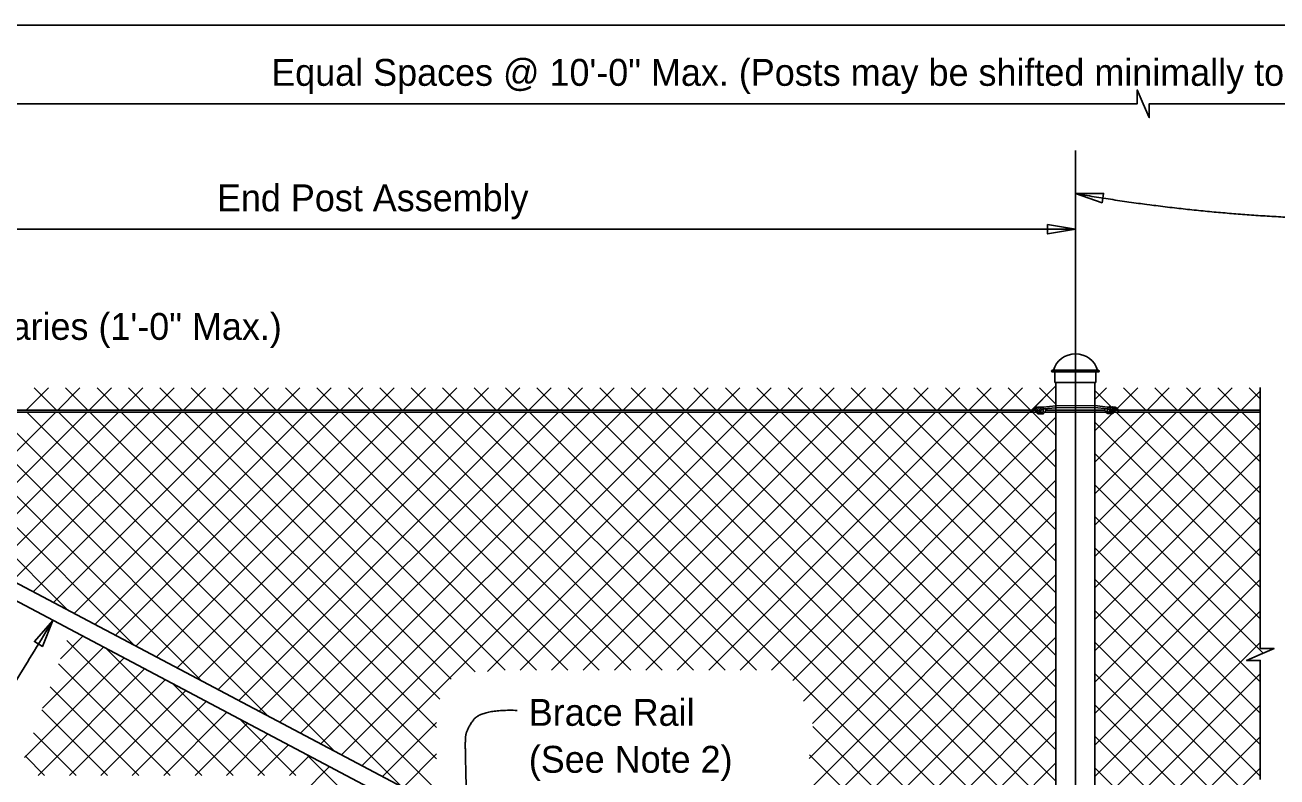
# Model space of a CAD drawing. Extents: x 0 to 72.1, y -15.2 to 30.1.
# Drawn here: x 6.75 to 16.14, y 22.36 to 28 of the extents above; entities that cross this region are included whole.
import ezdxf

# ---------------------------------------------------------------- set-up
doc = ezdxf.new("R2010")
doc.units = 0
for name, color, linetype in [('ActivePts-ConstElements', 7, 'Continuous'), ('Border', 7, 'Continuous'), ('Patterning', 7, 'Continuous'), ('PlotBorder_dp', 7, 'Continuous'), ('SheetBorder_dp', 7, 'Continuous'), ('SheetLines_dp', 7, 'Continuous'), ('TextMisc', 7, 'Continuous')]:
    doc.layers.add(name, color=color, linetype=linetype)

msp = doc.modelspace()

# ---------------------------------------------------------------- linework, layer by layer
at = {"layer": 'ActivePts-ConstElements'}
msp.add_lwpolyline([(0.016, 2.0538), (41.0666, 2.0538), (41.0666, 27.9999), (0.016, 27.9999)], close=True, dxfattribs=at)
at = {"layer": 'Border'}
for p, q in [((14.4852, 25.1116), (14.7769, 25.1116)), ((14.4852, 25.0969), (14.7769, 25.0969))]:
    msp.add_line(p, q, dxfattribs=at)
at = {"layer": 'Patterning'}
for p, q in [((6.761, 25.1116), (6.9276, 25.2783)), ((6.8202, 25.2783), (6.9869, 25.1116)), ((6.9967, 25.1116), (7.1633, 25.2783)), ((7.0559, 25.2783), (7.2226, 25.1116)), ((7.2324, 25.1116), (7.3991, 25.2783)), ((7.2916, 25.2783), (7.4583, 25.1116)), ((7.4681, 25.1116), (7.6348, 25.2783)), ((7.5273, 25.2783), (7.694, 25.1116)), ((7.7038, 25.1116), (7.8705, 25.2783)), ((7.763, 25.2783), (7.9297, 25.1116)), ((7.9395, 25.1116), (8.1062, 25.2783)), ((7.9987, 25.2783), (8.1654, 25.1116)), ((8.1752, 25.1116), (8.3419, 25.2783)), ((8.2344, 25.2783), (8.4011, 25.1116)), ((8.4109, 25.1116), (8.5776, 25.2783)), ((8.4701, 25.2783), (8.6368, 25.1116)), ((8.6466, 25.1116), (8.8133, 25.2783)), ((8.7058, 25.2783), (8.8725, 25.1116)), ((8.8823, 25.1116), (9.049, 25.2783)), ((8.9415, 25.2783), (9.1082, 25.1116)), ((9.118, 25.1116), (9.2847, 25.2783)), ((9.1772, 25.2783), (9.3439, 25.1116)), ((9.3537, 25.1116), (9.5204, 25.2783)), ((9.4129, 25.2783), (9.5796, 25.1116)), ((9.5894, 25.1116), (9.7561, 25.2783)), ((9.6486, 25.2783), (9.8153, 25.1116)), ((9.8251, 25.1116), (9.9918, 25.2783)), ((9.8843, 25.2783), (10.051, 25.1116)), ((10.0608, 25.1116), (10.2275, 25.2783)), ((10.12, 25.2783), (10.2867, 25.1116)), ((10.2965, 25.1116), (10.4632, 25.2783)), ((10.3557, 25.2783), (10.5224, 25.1116)), ((10.5322, 25.1116), (10.6989, 25.2783)), ((10.5914, 25.2783), (10.7581, 25.1116)), ((10.7679, 25.1116), (10.9346, 25.2783)), ((10.8271, 25.2783), (10.9938, 25.1116)), ((11.0036, 25.1116), (11.1703, 25.2783)), ((11.0628, 25.2783), (11.2295, 25.1116)), ((11.2393, 25.1116), (11.406, 25.2783)), ((11.2985, 25.2783), (11.4652, 25.1116)), ((11.475, 25.1116), (11.6417, 25.2783)), ((11.5342, 25.2783), (11.7009, 25.1116)), ((11.7107, 25.1116), (11.8774, 25.2783)), ((11.7699, 25.2783), (11.9366, 25.1116)), ((11.9464, 25.1116), (12.1131, 25.2783)), ((12.0057, 25.2783), (12.1723, 25.1116)), ((12.1821, 25.1116), (12.3488, 25.2783)), ((12.2414, 25.2783), (12.408, 25.1116)), ((12.352, 23.1602), (14.4852, 25.2934)), ((12.4178, 25.1116), (12.5845, 25.2783)), ((12.4771, 25.2783), (12.6437, 25.1116)), ((12.6535, 25.1116), (12.8202, 25.2783)), ((12.7128, 25.2783), (12.8794, 25.1116)), ((12.8892, 25.1116), (13.0559, 25.2783)), ((12.9485, 25.2783), (13.1151, 25.1116)), ((13.1249, 25.1116), (13.2916, 25.2783)), ((13.1842, 25.2783), (13.3508, 25.1116)), ((13.3606, 25.1116), (13.5273, 25.2783)), ((13.4199, 25.2783), (13.5865, 25.1116)), ((13.5963, 25.1116), (13.763, 25.2783)), ((13.6556, 25.2783), (13.8222, 25.1116)), ((13.832, 25.1116), (13.9987, 25.2783)), ((13.8913, 25.2783), (14.0579, 25.1116)), ((14.0677, 25.1116), (14.2344, 25.2783)), ((14.127, 25.2783), (14.2936, 25.1116)), ((14.3035, 25.1116), (14.4701, 25.2783)), ((14.3627, 25.2783), (14.4852, 25.1557)), ((14.7769, 25.1917), (14.8635, 25.2783)), ((14.9441, 25.1232), (15.0992, 25.2783)), ((14.9918, 25.2783), (15.1584, 25.1116)), ((15.1682, 25.1116), (15.3349, 25.2783)), ((15.2275, 25.2783), (15.3941, 25.1116)), ((15.4039, 25.1116), (15.5706, 25.2783)), ((15.4632, 25.2783), (15.6298, 25.1116)), ((15.6396, 25.1116), (15.8063, 25.2783)), ((15.6989, 25.2783), (15.8655, 25.1116)), ((15.9346, 25.2783), (16.018, 25.1949)), ((14.7769, 25.2575), (14.8992, 25.1352)), ((15.8753, 25.1116), (16.018, 25.2543)), ((5.8231, 25.0969), (7.5737, 23.3463)), ((6.0412, 24.1562), (6.9819, 25.0969)), ((6.0588, 25.0969), (8.0736, 23.0821)), ((6.1954, 24.0747), (7.2176, 25.0969)), ((6.2945, 25.0969), (8.5734, 22.818)), ((6.3496, 23.9932), (7.4533, 25.0969)), ((6.5038, 23.9117), (7.689, 25.0969)), ((6.5302, 25.0969), (9.0733, 22.5538)), ((6.658, 23.8302), (7.9247, 25.0969)), ((6.7659, 25.0969), (9.5731, 22.2897)), ((6.8122, 23.7487), (8.1604, 25.0969)), ((6.9665, 23.6672), (8.3961, 25.0969)), ((7.0016, 25.0969), (9.8384, 22.2601)), ((7.1207, 23.5857), (8.6318, 25.0969)), ((7.2373, 25.0969), (9.8384, 22.4958)), ((7.2749, 23.5042), (8.8675, 25.0969)), ((7.4291, 23.4227), (9.1033, 25.0969)), ((7.473, 25.0969), (9.8384, 22.7315)), ((7.5833, 23.3412), (9.339, 25.0969)), ((7.7087, 25.0969), (9.8627, 22.9429)), ((7.7375, 23.2597), (9.5747, 25.0969)), ((7.8917, 23.1782), (9.8104, 25.0969)), ((7.9444, 25.0969), (9.9473, 23.0941)), ((8.0459, 23.0968), (10.0461, 25.0969)), ((8.1801, 25.0969), (10.1284, 23.1486)), ((8.2001, 23.0153), (10.2818, 25.0969)), ((8.3543, 22.9338), (10.5175, 25.0969)), ((8.4158, 25.0969), (10.3525, 23.1602)), ((8.5085, 22.8523), (10.7532, 25.0969)), ((8.6515, 25.0969), (10.5883, 23.1602)), ((8.6628, 22.7708), (10.9889, 25.0969)), ((8.817, 22.6893), (11.2246, 25.0969)), ((8.8872, 25.0969), (10.824, 23.1602)), ((8.9712, 22.6078), (11.4603, 25.0969)), ((9.1229, 25.0969), (11.0597, 23.1602)), ((9.1254, 22.5263), (11.696, 25.0969)), ((9.2796, 22.4448), (11.9317, 25.0969)), ((9.3586, 25.0969), (11.2954, 23.1602)), ((9.5943, 25.0969), (11.5311, 23.1602)), ((9.83, 25.0969), (11.7668, 23.1602)), ((10.0657, 25.0969), (12.0025, 23.1602)), ((10.2203, 23.1498), (12.1674, 25.0969)), ((10.3015, 25.0969), (12.2382, 23.1602)), ((10.4664, 23.1602), (12.4031, 25.0969)), ((10.5372, 25.0969), (14.4852, 21.1488)), ((10.7021, 23.1602), (12.6388, 25.0969)), ((10.7729, 25.0969), (14.4852, 21.3845)), ((10.9378, 23.1602), (12.8745, 25.0969)), ((11.0086, 25.0969), (14.4852, 21.6202)), ((11.1735, 23.1602), (13.1102, 25.0969)), ((11.2443, 25.0969), (14.4852, 21.8559)), ((11.4092, 23.1602), (13.3459, 25.0969)), ((11.48, 25.0969), (14.4852, 22.0916)), ((11.6449, 23.1602), (13.5816, 25.0969)), ((11.7157, 25.0969), (14.4852, 22.3273)), ((11.8806, 23.1602), (13.8173, 25.0969)), ((11.9514, 25.0969), (14.4852, 22.563)), ((12.1163, 23.1602), (14.053, 25.0969)), ((12.1163, 23.1602), (14.053, 25.0969)), ((12.1871, 25.0969), (14.4852, 22.7987)), ((12.4228, 25.0969), (14.4852, 23.0344)), ((12.6585, 25.0969), (14.4852, 23.2701)), ((12.8942, 25.0969), (14.4852, 23.5058)), ((13.1299, 25.0969), (14.4852, 23.7415)), ((13.3656, 25.0969), (14.4852, 23.9772)), ((13.6013, 25.0969), (14.4852, 24.2129)), ((13.837, 25.0969), (14.4852, 24.4486)), ((14.0727, 25.0969), (14.4852, 24.6843)), ((14.3084, 25.0969), (14.4852, 24.92)), ((14.7769, 24.0132), (15.8606, 25.0969)), ((14.7769, 24.4846), (15.3892, 25.0969)), ((14.7769, 24.7203), (15.1535, 25.0969)), ((14.7769, 24.956), (14.9064, 25.0855)), ((14.7813, 24.2534), (15.6249, 25.0969)), ((14.9325, 25.1116), (14.937, 25.1161)), ((14.9375, 25.0969), (16.018, 24.0164)), ((15.1732, 25.0969), (16.018, 24.2521)), ((15.4089, 25.0969), (16.018, 24.4878)), ((15.6446, 25.0969), (16.018, 24.7235)), ((15.8803, 25.0969), (16.018, 24.9592)), ((12.5111, 23.0836), (14.4852, 25.0577)), ((14.7769, 25.0218), (16.018, 23.7807)), ((14.7769, 23.7775), (16.018, 25.0186)), ((5.7678, 24.9165), (7.0739, 23.6104)), ((12.5916, 22.9284), (14.4852, 24.822)), ((14.7769, 24.7861), (16.018, 23.545)), ((14.7769, 23.5418), (16.018, 24.7829)), ((12.6599, 22.761), (14.4852, 24.5863)), ((14.7769, 24.5503), (16.0391, 23.2882)), ((14.7769, 23.3061), (16.018, 24.5472)), ((12.6327, 22.4981), (14.4852, 24.3506)), ((14.7769, 24.3146), (16.018, 23.0736)), ((14.7769, 23.0704), (16.018, 24.3115)), ((11.5927, 21.2224), (14.4852, 24.1149)), ((14.7769, 24.0789), (16.018, 22.8379)), ((14.7769, 22.8347), (16.018, 24.0758)), ((11.7469, 21.1409), (14.4852, 23.8792)), ((14.7769, 23.8432), (16.018, 22.6022)), ((14.7769, 22.599), (16.018, 23.8401)), ((11.9012, 21.0594), (14.4852, 23.6435)), ((14.7769, 23.6075), (16.018, 22.3665)), ((14.7769, 22.3633), (16.018, 23.6044)), ((7.0166, 23.246), (7.1861, 23.4155)), ((12.0554, 20.9779), (14.4852, 23.4078)), ((6.8822, 22.8758), (7.3403, 23.334)), ((7.0662, 23.3824), (8.0769, 22.3717)), ((7.3615, 23.3228), (8.3126, 22.3717)), ((14.7769, 23.3718), (16.018, 22.1307)), ((14.7769, 22.1276), (16.018, 23.3687)), ((6.7477, 22.5056), (7.4945, 23.2525)), ((7.0034, 23.2095), (7.8412, 22.3717)), ((6.8494, 22.3717), (7.6488, 23.171)), ((12.2096, 20.8964), (14.4852, 23.1721)), ((14.7769, 23.1361), (16.018, 21.895)), ((14.7769, 21.8919), (16.018, 23.133)), ((6.9406, 23.0366), (7.6055, 22.3717)), ((7.0851, 22.3717), (7.803, 23.0895)), ((7.8614, 23.0586), (8.5483, 22.3717)), ((7.3208, 22.3717), (7.9572, 23.008)), ((7.5565, 22.3717), (8.1114, 22.9265)), ((12.3638, 20.815), (14.4852, 22.9364)), ((6.8778, 22.8637), (7.3698, 22.3717)), ((7.7922, 22.3717), (8.2656, 22.845)), ((14.7769, 22.9004), (16.018, 21.6593)), ((14.7769, 21.6562), (16.018, 22.8973)), ((8.0279, 22.3717), (8.4198, 22.7635)), ((8.3612, 22.7945), (8.784, 22.3717)), ((9.4338, 22.3633), (9.8384, 22.768)), ((12.6609, 22.7374), (14.4852, 20.9131)), ((6.815, 22.6908), (7.1341, 22.3717)), ((8.2636, 22.3717), (8.574, 22.682)), ((12.518, 20.7335), (14.4852, 22.7007)), ((14.7769, 22.6647), (16.018, 21.4236)), ((14.7769, 21.4205), (16.018, 22.6616)), ((8.4993, 22.3717), (8.7282, 22.6006)), ((6.7521, 22.5179), (6.8984, 22.3717)), ((8.735, 22.3717), (8.8824, 22.5191)), ((8.861, 22.5304), (11.9317, 19.4597)), ((9.588, 22.2818), (9.8384, 22.5323)), ((12.6374, 22.5252), (14.4852, 20.6774)), ((12.6722, 20.652), (14.4852, 22.465)), ((8.8306, 22.2315), (9.0367, 22.4376)), ((14.7769, 22.429), (15.9555, 21.2505)), ((14.7769, 21.1848), (16.018, 22.4259))]:
    msp.add_line(p, q, dxfattribs=at)
at = {"layer": 'PlotBorder_dp'}
for p, q in [((0.2512, 27.4094), (13.631, 27.4094)), ((4.631, 26.4684), (14.631, 26.4684))]:
    msp.add_line(p, q, dxfattribs=at)
for points in [[(13.631, 27.4094), (15.0947, 27.4094), (15.0947, 27.5128), (15.1397, 27.4094), (15.1847, 27.3061), (15.1847, 27.4094), (28.4756, 27.4094)], [(16.018, 25.2804), (16.018, 23.3241), (16.1214, 23.3241), (16.018, 23.2791), (15.9147, 23.2341), (16.018, 23.2341), (16.018, 22.3405)]]:
    msp.add_lwpolyline(points, dxfattribs=at)
for points in [[(14.631, 26.7353), (14.831, 26.6673), (14.8423, 26.737)], [(14.631, 26.4684), (14.4228, 26.5037), (14.4228, 26.4332)], [(6.961, 23.5344), (6.8219, 23.3754), (6.8821, 23.3385)]]:
    msp.add_lwpolyline(points, close=True, dxfattribs=at)
for points in [[(18.6126, 26.5365), (17.8093, 26.5365), (16.42, 26.5365), (15.2385, 26.6311), (14.631, 26.7352)], [(6.6335, 22.1348), (6.5026, 22.1207), (6.3196, 22.188), (6.3281, 22.5146), (6.961, 23.5344)], [(10.4442, 22.859), (10.1746, 22.8671), (10.0565, 22.7087), (10.0536, 22.5875), (10.0582, 22.4197), (10.0663, 22.0067)]]:
    msp.add_open_spline(points, degree=2, dxfattribs=at)
at = {"layer": 'SheetBorder_dp'}
msp.add_line((14.631, 27.059), (14.631, 16.8122), dxfattribs=at)
at = {"layer": 'TextMisc'}
for p, q in [((14.4587, 25.4103), (14.8033, 25.4103)), ((14.8033, 25.398), (14.4587, 25.398)), ((14.477, 25.3183), (14.477, 25.398)), ((14.7851, 25.3183), (14.7851, 25.398)), ((14.7851, 25.3183), (14.477, 25.3183)), ((14.4852, 19.6731), (14.4852, 25.3183)), ((14.7769, 19.6731), (14.7769, 25.3183)), ((5.8212, 25.1116), (14.3101, 25.1116)), ((5.8212, 25.0969), (14.3367, 25.0969)), ((14.32, 25.1116), (14.3332, 25.1116)), ((14.4852, 25.1443), (14.3904, 25.1332)), ((14.4852, 25.1297), (14.3926, 25.1202)), ((14.4016, 25.0969), (14.4852, 25.0969)), ((14.4031, 25.1116), (14.4852, 25.1116)), ((14.4852, 25.1443), (14.7764, 25.1459)), ((14.4852, 25.1297), (14.7764, 25.1314)), ((14.7764, 25.1459), (14.8707, 25.1348)), ((14.7764, 25.1314), (14.8685, 25.122)), ((14.7769, 25.1116), (14.8573, 25.1116)), ((14.7769, 25.0969), (14.86, 25.0969)), ((14.9227, 25.0969), (16.018, 25.0969)), ((14.9276, 25.1116), (14.9429, 25.1116)), ((14.9514, 25.1116), (16.018, 25.1116)), ((14.2837, 19.8004), (5.0341, 24.6884)), ((14.2277, 19.6944), (4.978, 24.5823))]:
    msp.add_line(p, q, dxfattribs=at)
for centre, start, end in [((14.4589, 25.404), 91.1647, 268.8353), ((14.8032, 25.404), 271.1647, 88.8353)]:
    msp.add_arc(centre, 0.00613, start, end, dxfattribs=at)
for centre, major_axis, ratio, start_param, end_param in [((14.6317, 25.3692), (0.1711, 0), 0.957868, 0.252602, 2.888574), ((14.3443, 25.0974), (0.0373, 0), 0.957868, 1.486836, 3.108042), ((14.3654, 25.0577), (-0.0724, 0), 0.957868, 5.162149, 5.652106), ((14.358, 25.1093), (-0.0249, 0), 0.957868, 6.009018, 7.089857), ((14.3568, 25.1119), (0.023, 0), 0.957868, 1.29026, 2.970541), ((14.3593, 25.1053), (0.0231, 0), 0.957868, 3.779554, 4.879821), ((14.3756, 25.1065), (0.0295, 0), 0.957868, 1.220941, 4.039556), ((14.389, 25.1083), (-0.0303, -0.0108), 0.724765, 4.35367, 6.324556), ((14.3654, 25.0997), (0.0206, -0.0021), 0.798607, 4.32653, 5.220153), ((14.3789, 25.0997), (0.0206, -0.0021), 0.798607, 3.333154, 5.220153), ((14.3857, 25.1042), (-0.0139, 0), 0.957868, 5.22362, 6.905413), ((14.3801, 25.1018), (-0.00795, 0), 0.957868, 6.140374, 9.314262), ((14.3941, 25.0953), (-0.0259, 0), 0.957868, 4.777514, 5.62749), ((14.3784, 25.1076), (0.0119, 0), 0.957868, 5.725876, 7.416677), ((14.3715, 25.1184), (0.0391, 0), 0.957868, 5.082588, 5.41974), ((14.3784, 25.1076), (0.0119, 0), 0.957868, 5.639684, 5.723117), ((14.3786, 25.1064), (0.0251, 0), 0.957868, 5.531357, 6.227833), ((14.3786, 25.1064), (0.0251, 0), 0.957868, 0.407687, 0.609214), ((14.8821, 25.1081), (-0.0251, 0), 0.957868, 0.055352, 0.751829), ((14.8821, 25.1081), (-0.0251, 0), 0.957868, 5.673972, 5.875498), ((14.8892, 25.1202), (-0.0391, 0), 0.957868, 0.863445, 1.200597), ((14.8717, 25.11), (0.0303, -0.0108), 0.724765, 6.241815, 8.212701), ((14.8666, 25.0971), (0.0259, 0), 0.957868, 0.655696, 1.505671), ((14.8823, 25.1094), (-0.0119, 0), 0.957868, 5.149694, 6.840495), ((14.8823, 25.1094), (-0.0119, 0), 0.957868, 0.560069, 0.643501), ((14.8807, 25.1036), (0.00795, 0), 0.957868, 3.252108, 6.425997), ((14.8818, 25.1014), (-0.0206, -0.0021), 0.798607, 1.063032, 2.950031), ((14.8851, 25.1082), (-0.0295, 0), 0.957868, 2.243629, 5.062245), ((14.875, 25.106), (0.0139, 0), 0.957868, 5.660958, 7.342751), ((14.8953, 25.1014), (-0.0206, -0.0021), 0.798607, 1.063032, 1.956656), ((14.9039, 25.1136), (-0.023, 0), 0.957868, 3.312645, 4.992926), ((14.9014, 25.1071), (-0.0231, 0), 0.957868, 1.403365, 2.503632), ((14.9164, 25.0992), (-0.0373, 0), 0.957868, 3.175144, 4.79635), ((14.9028, 25.1111), (0.0249, 0), 0.957868, 5.476514, 6.557353), ((14.8953, 25.0595), (0.0724, 0), 0.957868, 0.631079, 1.121037)]:
    msp.add_ellipse(centre, major_axis=major_axis, ratio=ratio, start_param=start_param, end_param=end_param, dxfattribs=at)

# ---------------------------------------------------------------- texts
at = {"layer": 'SheetLines_dp'}
for s, p in [('Equal Spaces @ 10\'-0" Max. (Posts may be shifted minimally to meet required clearances)', (8.5986, 27.544)), ('End Post Assembly', (8.1913, 26.603)), ('Varies (1\'-0" Max.)', (6.4634, 25.6385)), ('Brace Rail', (10.5307, 22.7433)), ('(See Note 2)', (10.5307, 22.3913))]:
    msp.add_text(s, height=0.2016, dxfattribs=at).set_placement(p)

doc.saveas('drawing.dxf')
